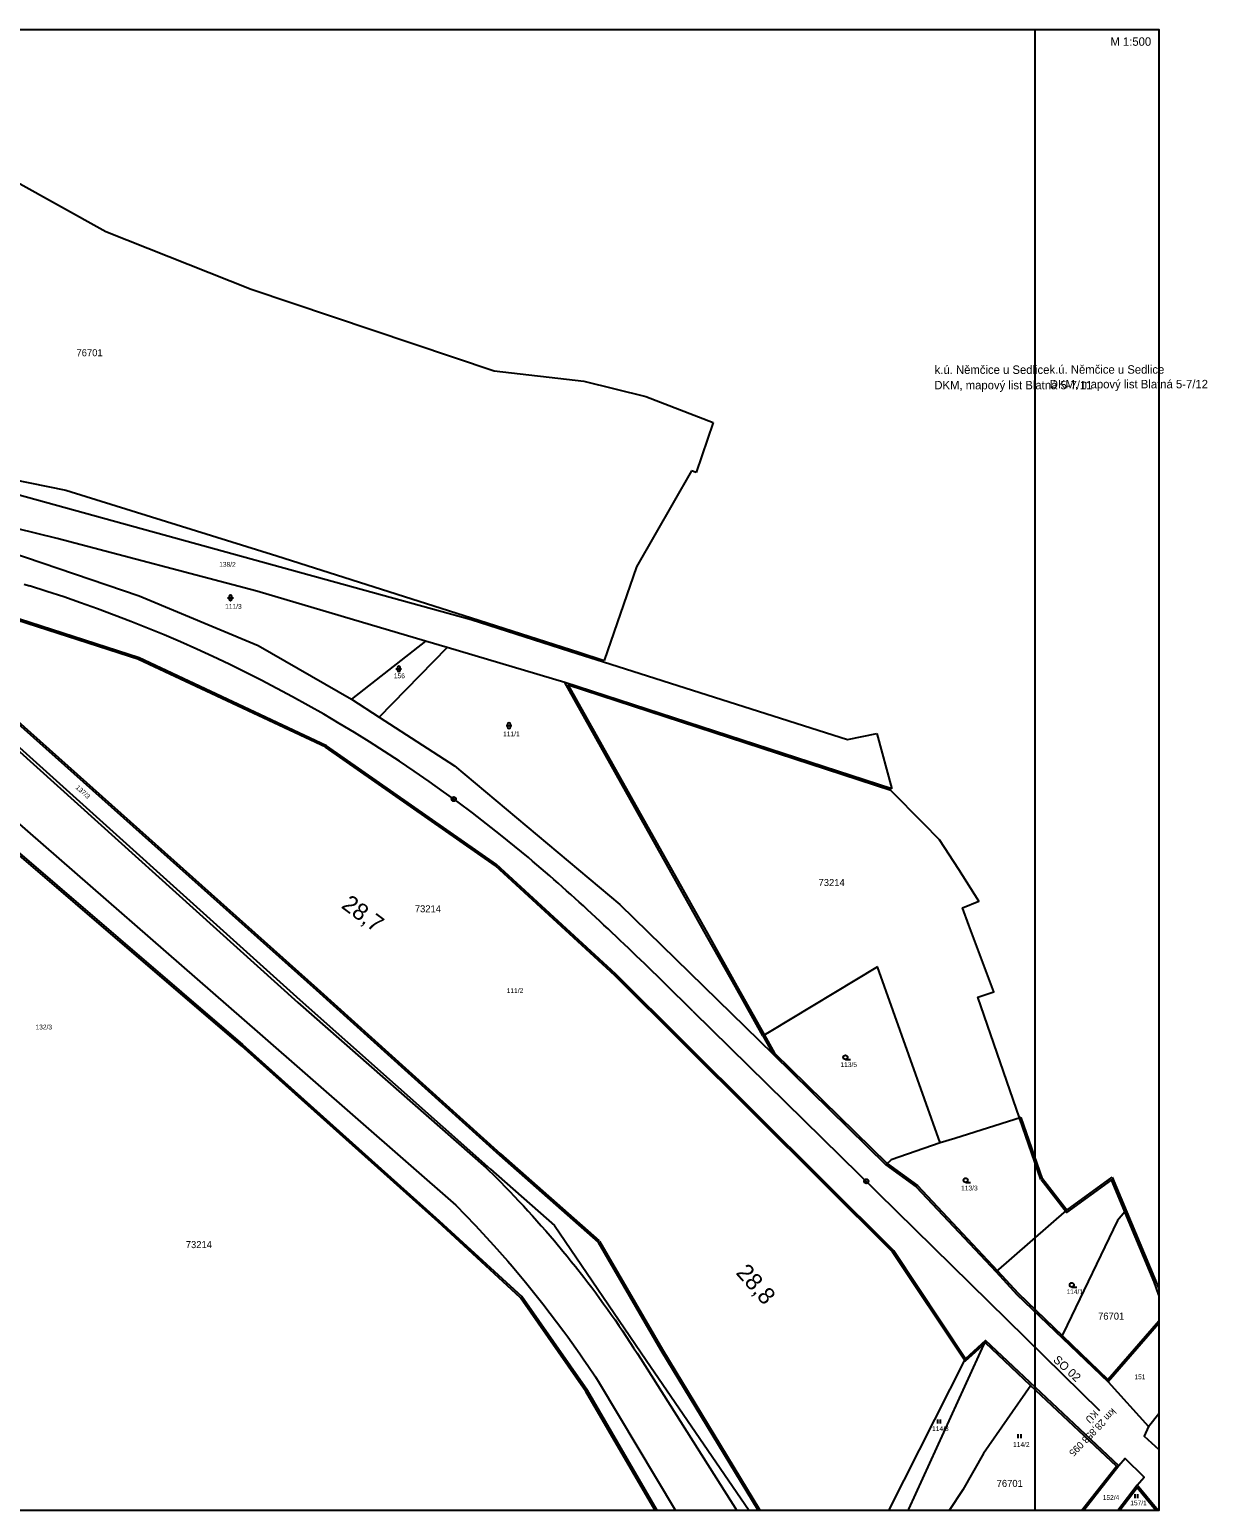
# Model space of a CAD drawing. Extents: x -792659 to -786947, y -1118170 to -1109641.
# Drawn here: x -789553.7 to -789344.4, y -1114466.8 to -1114203.8 of the extents above; entities that cross this region are included whole.
import ezdxf

# ---------------------------------------------------------------- set-up
doc = ezdxf.new("R2010")
doc.units = 0
doc.layers.add('1', color=7, linetype='Continuous')
doc.layers.add('Značky kultur', color=7, linetype='Continuous')

msp = doc.modelspace()

# ---------------------------------------------------------------- linework, layer by layer
at = {"layer": '1'}
for p, q in [((-789375, -1114466.81), (-789375, -1114203.77)), ((-789556.43, -1114230.59), (-789540.11, -1114239.63)), ((-789540.11, -1114239.63), (-789514.28, -1114249.87)), ((-789514.28, -1114249.87), (-789471.09, -1114264.39)), ((-789471.09, -1114264.39), (-789455.16, -1114266.24)), ((-789455.16, -1114266.24), (-789444.18, -1114268.92)), ((-789444.18, -1114268.92), (-789432.19, -1114273.58)), ((-789432.19, -1114273.58), (-789435.21, -1114282.44)), ((-789562.23, -1114284.54), (-789475.21, -1114308.57)), ((-789436.06, -1114282.16), (-789445.82, -1114299.21)), ((-789435.21, -1114282.44), (-789436.06, -1114282.16)), ((-789548.79, -1114294.18), (-789562.23, -1114290.83)), ((-789513.31, -1114303.51), (-789548.79, -1114294.18)), ((-789557.19, -1114296.51), (-789534.19, -1114304.37)), ((-789445.82, -1114299.21), (-789451.57, -1114315.81)), ((-789534.19, -1114304.37), (-789513.07, -1114313.2)), ((-789483.32, -1114312.4), (-789513.31, -1114303.51)), ((-789534.27, -1114315.67), (-789561.47, -1114306.89)), ((-789534.18, -1114315.38), (-789561.38, -1114306.6)), ((-789475.21, -1114308.57), (-789456.17, -1114314.65)), ((-789513.07, -1114313.2), (-789496.46, -1114322.71)), ((-789483.32, -1114312.4), (-789496.46, -1114322.71)), ((-789491.56, -1114325.89), (-789479.44, -1114313.55)), ((-789479.44, -1114313.55), (-789483.32, -1114312.4)), ((-789458.58, -1114319.72), (-789479.44, -1114313.55)), ((-789501.04, -1114331.26), (-789534.31, -1114315.65)), ((-789500.91, -1114330.99), (-789534.18, -1114315.38)), ((-789456.17, -1114314.65), (-789451.67, -1114316.09)), ((-789451.67, -1114316.09), (-789408.31, -1114329.88)), ((-789562.1, -1114321.39), (-789502.74, -1114374.33)), ((-789561.9, -1114321.17), (-789502.54, -1114374.11)), ((-789433.25, -1114364.91), (-789458.58, -1114319.72)), ((-789400.45, -1114338.66), (-789458.58, -1114319.72)), ((-789496.46, -1114322.71), (-789491.56, -1114325.89)), ((-789563.81, -1114324.53), (-789505.98, -1114376.61)), ((-789562.23, -1114325.2), (-789505.63, -1114376.09)), ((-789491.56, -1114325.89), (-789478.18, -1114334.57)), ((-789408.31, -1114329.88), (-789403.1, -1114328.81)), ((-789403.1, -1114328.81), (-789400.45, -1114338.66)), ((-789470.85, -1114352.34), (-789501.08, -1114331.24)), ((-789470.68, -1114352.09), (-789500.91, -1114330.99)), ((-789478.18, -1114334.57), (-789448.8, -1114359.16)), ((-789562.23, -1114339.03), (-789512.77, -1114382.14)), ((-789562.23, -1114344.31), (-789515.81, -1114384.07)), ((-789449.67, -1114371.78), (-789470.88, -1114352.31)), ((-789449.47, -1114371.56), (-789470.68, -1114352.09)), ((-789448.8, -1114359.16), (-789421.56, -1114385.77)), ((-789428.26, -1114373.81), (-789433.25, -1114364.91)), ((-789400.13, -1114420.69), (-789449.47, -1114371.56)), ((-789402.98, -1114370.28), (-789422.27, -1114381.87)), ((-789391.84, -1114401.52), (-789402.98, -1114370.28)), ((-789502.54, -1114374.11), (-789469.97, -1114403.5)), ((-789400.34, -1114420.9), (-789449.68, -1114371.77)), ((-789423.37, -1114382.53), (-789428.26, -1114373.81)), ((-789505.98, -1114376.61), (-789472.53, -1114405.97)), ((-789505.63, -1114376.09), (-789471.74, -1114406.17)), ((-789502.74, -1114374.33), (-789470.17, -1114403.72)), ((-789435.79, -1114378.12), (-789363.55, -1114449.05)), ((-789435.79, -1114378.12), (-789363.55, -1114449.05)), ((-789435.79, -1114378.12), (-789363.55, -1114449.05)), ((-789422.27, -1114381.87), (-789423.37, -1114382.53)), ((-789515.81, -1114384.07), (-789480.88, -1114415.35)), ((-789512.77, -1114382.14), (-789477.93, -1114412.6)), ((-789423.37, -1114382.53), (-789421.56, -1114385.77)), ((-789421.56, -1114385.77), (-789401.5, -1114405.4)), ((-789377.47, -1114397), (-789389.24, -1114400.76)), ((-789373.69, -1114407.91), (-789377.47, -1114397)), ((-789391.84, -1114401.52), (-789400.58, -1114404.52)), ((-789389.24, -1114400.76), (-789391.84, -1114401.52)), ((-789470.17, -1114403.72), (-789452.65, -1114419.15)), ((-789469.97, -1114403.49), (-789452.45, -1114418.92)), ((-789400.58, -1114404.52), (-789401.5, -1114405.4)), ((-789401.5, -1114405.4), (-789396.12, -1114409.35)), ((-789472.53, -1114405.97), (-789470.84, -1114407.63)), ((-789471.74, -1114406.17), (-789460.39, -1114416.23)), ((-789470.84, -1114407.63), (-789470.01, -1114408.47)), ((-789369.37, -1114413.5), (-789373.69, -1114407.91)), ((-789369.37, -1114413.5), (-789361.3, -1114407.6)), ((-789361.3, -1114407.6), (-789353, -1114427.42)), ((-789470.01, -1114408.47), (-789469.18, -1114409.31)), ((-789469.18, -1114409.31), (-789468.35, -1114410.16)), ((-789468.35, -1114410.16), (-789467.54, -1114411.01)), ((-789467.54, -1114411.01), (-789466.72, -1114411.87)), ((-789396.12, -1114409.35), (-789381.93, -1114424.44)), ((-789477.93, -1114412.6), (-789474.5, -1114416.13)), ((-789466.72, -1114411.87), (-789465.91, -1114412.73)), ((-789465.91, -1114412.73), (-789465.11, -1114413.6)), ((-789465.11, -1114413.6), (-789464.32, -1114414.48)), ((-789381.93, -1114424.44), (-789369.37, -1114413.5)), ((-789480.88, -1114415.35), (-789466.19, -1114428.84)), ((-789474.5, -1114416.13), (-789471.16, -1114419.75)), ((-789464.32, -1114414.48), (-789463.53, -1114415.36)), ((-789463.53, -1114415.36), (-789462.74, -1114416.24)), ((-789462.74, -1114416.24), (-789461.96, -1114417.13)), ((-789460.39, -1114416.23), (-789444.12, -1114440.1)), ((-789360.35, -1114415.34), (-789369.28, -1114433.92)), ((-789359.04, -1114413.79), (-789360.35, -1114415.34)), ((-789461.96, -1114417.13), (-789461.19, -1114418.02)), ((-789461.19, -1114418.02), (-789460.42, -1114418.92)), ((-789460.42, -1114418.92), (-789458.9, -1114420.74)), ((-789471.16, -1114419.75), (-789468.71, -1114422.52)), ((-789458.9, -1114420.74), (-789458.15, -1114421.65)), ((-789452.65, -1114419.15), (-789441.48, -1114438.37)), ((-789452.39, -1114419), (-789441.22, -1114438.22)), ((-789387.36, -1114439.86), (-789400.13, -1114420.69)), ((-789468.71, -1114422.52), (-789467.91, -1114423.45)), ((-789467.91, -1114423.45), (-789465.54, -1114426.27)), ((-789458.15, -1114421.65), (-789457.41, -1114422.57)), ((-789457.41, -1114422.57), (-789456.67, -1114423.5)), ((-789456.67, -1114423.5), (-789455.21, -1114425.36)), ((-789465.54, -1114426.27), (-789462.45, -1114430.11)), ((-789455.21, -1114425.36), (-789454.49, -1114426.3)), ((-789454.49, -1114426.3), (-789453.78, -1114427.24)), ((-789381.93, -1114424.44), (-789378.22, -1114428.46)), ((-789454.55, -1114445.52), (-789466.19, -1114428.84)), ((-789453.78, -1114427.24), (-789453.07, -1114428.19)), ((-789453.07, -1114428.19), (-789452.37, -1114429.14)), ((-789452.37, -1114429.14), (-789451.67, -1114430.09)), ((-789378.22, -1114428.46), (-789362.04, -1114444)), ((-789378.01, -1114428.24), (-789361.83, -1114443.78)), ((-789462.45, -1114430.11), (-789458.74, -1114435.02)), ((-789451.67, -1114430.09), (-789450.98, -1114431.06)), ((-789450.98, -1114431.06), (-789450.3, -1114432.02)), ((-789450.3, -1114432.02), (-789449.62, -1114432.99)), ((-789449.62, -1114432.99), (-789448.95, -1114433.97)), ((-789448.95, -1114433.97), (-789448.29, -1114434.94)), ((-789369.28, -1114433.92), (-789370.2, -1114435.75)), ((-789353, -1114433.59), (-789362.04, -1114444)), ((-789458.74, -1114435.02), (-789458.01, -1114436.01)), ((-789458.01, -1114436.01), (-789457.29, -1114437.01)), ((-789457.29, -1114437.01), (-789456.58, -1114438.02)), ((-789448.29, -1114434.94), (-789448.29, -1114434.94)), ((-789448.29, -1114434.94), (-789446.98, -1114436.91)), ((-789446.98, -1114436.91), (-789446.33, -1114437.91)), ((-789383.79, -1114436.65), (-789397.47, -1114466.61)), ((-789383.79, -1114436.65), (-789387.36, -1114439.86)), ((-789360.15, -1114458.92), (-789383.79, -1114436.65)), ((-789456.58, -1114438.02), (-789455.88, -1114439.02)), ((-789455.88, -1114439.02), (-789455.18, -1114440.04)), ((-789446.33, -1114437.91), (-789445.69, -1114438.9)), ((-789445.69, -1114438.9), (-789445.06, -1114439.9)), ((-789445.06, -1114439.9), (-789427.97, -1114466.81)), ((-789441.48, -1114438.37), (-789424.2, -1114466.81)), ((-789441.22, -1114438.21), (-789423.95, -1114466.65)), ((-789401, -1114466.81), (-789387.36, -1114439.86)), ((-789455.18, -1114440.04), (-789454.48, -1114441.05)), ((-789454.48, -1114441.05), (-789453.11, -1114443.1)), ((-789444.12, -1114440.1), (-789425.82, -1114466.81)), ((-789453.11, -1114443.1), (-789452.44, -1114444.13)), ((-789452.44, -1114444.13), (-789438.87, -1114466.81)), ((-789375.75, -1114444.64), (-789384.14, -1114456.72)), ((-789362.04, -1114444), (-789354.83, -1114451.89)), ((-789442.15, -1114466.81), (-789454.55, -1114445.52)), ((-789354.83, -1114451.89), (-789353, -1114449.6)), ((-789354.83, -1114451.89), (-789355.6, -1114453.64)), ((-789355.6, -1114453.64), (-789353, -1114455.98)), ((-789384.14, -1114456.72), (-789387.82, -1114463.14)), ((-789359, -1114457.59), (-789360.15, -1114458.92)), ((-789355.65, -1114460.93), (-789359, -1114457.59)), ((-789360.15, -1114458.92), (-789366.36, -1114466.81)), ((-789356.86, -1114462.31), (-789355.65, -1114460.93)), ((-789387.82, -1114463.14), (-789390.27, -1114466.81)), ((-789356.86, -1114462.31), (-789360.31, -1114466.81)), ((-789353.13, -1114466.81), (-789356.86, -1114462.31)), ((-789397.47, -1114466.61), (-789397.6, -1114466.81))]:
    msp.add_line(p, q, dxfattribs=at)
msp.add_lwpolyline([(-789729.37, -1114203.77), (-789353, -1114203.77), (-789353, -1114466.81), (-789729.37, -1114466.81)], close=True, dxfattribs=at)
for points in [[(-789674.01, -1114222.23), (-789653.09, -1114241.04), (-789626.09, -1114265.17), (-789585.65, -1114277.76), (-789547.21, -1114285.57), (-789509.71, -1114297.22), (-789475.12, -1114308.28), (-789456.08, -1114314.36), (-789451.57, -1114315.81)], [(-789557.19, -1114296.51), (-789534.19, -1114304.37), (-789513.07, -1114313.2), (-789496.46, -1114322.71), (-789491.56, -1114325.89), (-789478.18, -1114334.57), (-789448.8, -1114359.16), (-789421.56, -1114385.77), (-789401.5, -1114405.4), (-789396.12, -1114409.35), (-789381.93, -1114424.44), (-789378.22, -1114428.46), (-789362.04, -1114444), (-789354.83, -1114451.89), (-789355.6, -1114453.64), (-789353, -1114455.98), (-789353, -1114466.81), (-789353.13, -1114466.81), (-789356.86, -1114462.31), (-789355.65, -1114460.93), (-789359, -1114457.59), (-789360.15, -1114458.92), (-789383.79, -1114436.65), (-789387.36, -1114439.86), (-789400.13, -1114420.69), (-789449.47, -1114371.56), (-789470.68, -1114352.09), (-789500.91, -1114330.99), (-789534.18, -1114315.38), (-789561.38, -1114306.6)], [(-789554.62, -1114302.3), (-789553.66, -1114302.59)], [(-789554.62, -1114302.3), (-789553.66, -1114302.59)], [(-789554.62, -1114302.3), (-789553.66, -1114302.59)], [(-789554.62, -1114302.3), (-789553.66, -1114302.59)], [(-789373.97, -1114408.01), (-789377.75, -1114397.1), (-789378.87, -1114393.82), (-789385.15, -1114375.67), (-789382.31, -1114374.69), (-789386.76, -1114362.85), (-789387.9, -1114359.79), (-789385.02, -1114358.6), (-789388.58, -1114352.99), (-789391.97, -1114347.67), (-789394.89, -1114344.71), (-789400.61, -1114338.92), (-789457.94, -1114320.24), (-789432.99, -1114364.76), (-789428, -1114373.66), (-789423.11, -1114382.38), (-789421.32, -1114385.59), (-789401.31, -1114405.17), (-789395.92, -1114409.12), (-789381.71, -1114424.24), (-789378.01, -1114428.25), (-789370.13, -1114435.81)], [(-789442.5, -1114466.81), (-789454.8, -1114445.68), (-789466.42, -1114429.04), (-789481.08, -1114415.57), (-789516.01, -1114384.3), (-789575.49, -1114333.35), (-789576.46, -1114335.45), (-789599.6, -1114385.9), (-789602.99, -1114393.32), (-789604.59, -1114396.8)], [(-789435.79, -1114378.12), (-789436.5, -1114377.42), (-789437.21, -1114376.72), (-789437.93, -1114376.02), (-789438.64, -1114375.32), (-789439.36, -1114374.62), (-789440.07, -1114373.92), (-789440.78, -1114373.22), (-789441.5, -1114372.52), (-789442.22, -1114371.82), (-789442.93, -1114371.13), (-789443.65, -1114370.43), (-789444.37, -1114369.73), (-789445.09, -1114369.04), (-789445.81, -1114368.34), (-789446.53, -1114367.65), (-789447.25, -1114366.96), (-789447.97, -1114366.27), (-789448.7, -1114365.58), (-789449.42, -1114364.89), (-789450.15, -1114364.2), (-789450.88, -1114363.52), (-789451.6, -1114362.83), (-789452.33, -1114362.15), (-789453.07, -1114361.47), (-789453.8, -1114360.79), (-789454.54, -1114360.11), (-789455.27, -1114359.44), (-789456.01, -1114358.76), (-789456.75, -1114358.09), (-789457.5, -1114357.42), (-789458.24, -1114356.75), (-789458.99, -1114356.09), (-789459.74, -1114355.42), (-789460.49, -1114354.76), (-789461.24, -1114354.11), (-789462, -1114353.45), (-789462.75, -1114352.8), (-789463.51, -1114352.15), (-789464.28, -1114351.5), (-789465.04, -1114350.86)], [(-789435.79, -1114378.12), (-789436.5, -1114377.42), (-789437.21, -1114376.72), (-789437.93, -1114376.02), (-789438.64, -1114375.32), (-789439.36, -1114374.62), (-789440.07, -1114373.92), (-789440.78, -1114373.22), (-789441.5, -1114372.52), (-789442.22, -1114371.82), (-789442.93, -1114371.13), (-789443.65, -1114370.43), (-789444.37, -1114369.73), (-789445.09, -1114369.04), (-789445.81, -1114368.34), (-789446.53, -1114367.65), (-789447.25, -1114366.96), (-789447.97, -1114366.27), (-789448.7, -1114365.58), (-789449.42, -1114364.89), (-789450.15, -1114364.2), (-789450.88, -1114363.52), (-789451.6, -1114362.83), (-789452.33, -1114362.15), (-789453.07, -1114361.47), (-789453.8, -1114360.79), (-789454.54, -1114360.11), (-789455.27, -1114359.44), (-789456.01, -1114358.76), (-789456.75, -1114358.09), (-789457.5, -1114357.42), (-789458.24, -1114356.75), (-789458.99, -1114356.09), (-789459.74, -1114355.42), (-789460.49, -1114354.76), (-789461.24, -1114354.11), (-789462, -1114353.45), (-789462.75, -1114352.8), (-789463.51, -1114352.15), (-789464.28, -1114351.5), (-789465.04, -1114350.86)], [(-789435.79, -1114378.12), (-789436.5, -1114377.42), (-789437.21, -1114376.72), (-789437.93, -1114376.02), (-789438.64, -1114375.32), (-789439.36, -1114374.62), (-789440.07, -1114373.92), (-789440.78, -1114373.22), (-789441.5, -1114372.52), (-789442.22, -1114371.82), (-789442.93, -1114371.13), (-789443.65, -1114370.43), (-789444.37, -1114369.73), (-789445.09, -1114369.04), (-789445.81, -1114368.34), (-789446.53, -1114367.65), (-789447.25, -1114366.96), (-789447.97, -1114366.27), (-789448.7, -1114365.58), (-789449.42, -1114364.89), (-789450.15, -1114364.2), (-789450.88, -1114363.52), (-789451.6, -1114362.83), (-789452.33, -1114362.15), (-789453.07, -1114361.47), (-789453.8, -1114360.79), (-789454.54, -1114360.11), (-789455.27, -1114359.44), (-789456.01, -1114358.76), (-789456.75, -1114358.09), (-789457.5, -1114357.42), (-789458.24, -1114356.75), (-789458.99, -1114356.09), (-789459.74, -1114355.42), (-789460.49, -1114354.76), (-789461.24, -1114354.11), (-789462, -1114353.45), (-789462.75, -1114352.8), (-789463.51, -1114352.15), (-789464.28, -1114351.5), (-789465.04, -1114350.86)], [(-789359.04, -1114413.79), (-789361.43, -1114408.07), (-789369.43, -1114413.91), (-789373.93, -1114408.09)], [(-789353, -1114428.57), (-789353.82, -1114426.24), (-789359.04, -1114413.79)], [(-789375.79, -1114444.61), (-789383.79, -1114437.06), (-789387.42, -1114440.32), (-789400.38, -1114420.86)], [(-789370.13, -1114435.81), (-789362.06, -1114443.57), (-789353, -1114433.13)], [(-789366.74, -1114466.81), (-789360.56, -1114458.95), (-789375.79, -1114444.61)], [(-789353.52, -1114466.81), (-789356.85, -1114462.79), (-789359.93, -1114466.81)]]:
    msp.add_lwpolyline(points, dxfattribs=at)
for centre in [(-789478.31, -1114340.46), (-789478.3, -1114340.45), (-789405.01, -1114408.35), (-789404.99, -1114408.34)]:
    msp.add_circle(centre, 0.375, dxfattribs=at)
msp.add_arc((-789628.9, -1114546.24), 255, 50.0141, 72.8377, dxfattribs=at)
msp.add_arc((-789628.9, -1114546.24), 255, 50.0141, 72.8377, dxfattribs=at)
msp.add_arc((-789628.9, -1114546.24), 255, 50.0141, 72.8377, dxfattribs=at)
at = {"layer": 'Značky kultur'}
for p, q in [((-789518.47, -1114304.73), (-789517.46, -1114304.73)), ((-789518.22, -1114304.48), (-789518.22, -1114304.98)), ((-789517.71, -1114304.98), (-789517.71, -1114304.48)), ((-789488.57, -1114317.31), (-789487.57, -1114317.31)), ((-789488.32, -1114317.06), (-789488.32, -1114317.56)), ((-789487.82, -1114317.56), (-789487.82, -1114317.06)), ((-789468.98, -1114327.41), (-789467.98, -1114327.41)), ((-789468.73, -1114327.16), (-789468.73, -1114327.66)), ((-789468.23, -1114327.66), (-789468.23, -1114327.16)), ((-789408.7, -1114386.72), (-789407.82, -1114386.72)), ((-789387.33, -1114408.55), (-789386.46, -1114408.55)), ((-789368.48, -1114427.14), (-789367.61, -1114427.14)), ((-789392.3, -1114451.4), (-789392.3, -1114450.65)), ((-789391.8, -1114451.4), (-789391.8, -1114450.65)), ((-789377.99, -1114454.01), (-789377.99, -1114453.26)), ((-789377.49, -1114454.01), (-789377.49, -1114453.26)), ((-789357.24, -1114464.65), (-789357.24, -1114463.9)), ((-789356.74, -1114464.65), (-789356.74, -1114463.9))]:
    msp.add_line(p, q, dxfattribs=at)
for centre in [(-789408.7, -1114386.34), (-789387.33, -1114408.17), (-789368.48, -1114426.76)]:
    msp.add_circle(centre, 0.375, dxfattribs=at)
for centre, start, end in [((-789517.97, -1114304.48), 0, 180), ((-789517.97, -1114304.97), 180, 359.9879), ((-789488.07, -1114317.06), 0, 180), ((-789488.07, -1114317.56), 180, 359.9879), ((-789468.48, -1114327.16), 0, 180), ((-789468.48, -1114327.66), 180, 359.9879)]:
    msp.add_arc(centre, 0.25, start, end, dxfattribs=at)

# ---------------------------------------------------------------- texts
at = {"layer": '1'}
for s, height, p in [('M 1:500', 1.5, (-789361.62, -1114206.64)), ('76701', 1.25, (-789545.33, -1114261.79)), ('k.ú. Němčice u Sedlice', 1.5, (-789392.85, -1114264.93)), ('k.ú. Němčice u Sedlice', 1.5, (-789372.44, -1114264.89)), ('DKM, mapový list Blatná 5-7/11', 1.5, (-789392.9, -1114267.67)), ('DKM, mapový list Blatná 5-7/12', 1.5, (-789372.38, -1114267.49)), ('138/2', 0.85, (-789519.97, -1114299.19)), ('111/3', 0.85, (-789518.91, -1114306.66)), ('156', 0.85, (-789488.94, -1114318.99)), ('111/1', 0.85, (-789469.52, -1114329.3)), ('73214', 1.25, (-789413.48, -1114355.91)), ('73214', 1.25, (-789485.21, -1114360.57)), ('111/2', 0.85, (-789468.87, -1114374.9)), ('132/3', 0.85, (-789552.61, -1114381.38)), ('113/5', 0.85, (-789409.58, -1114388.05)), ('113/3', 0.85, (-789388.14, -1114409.98)), ('73214', 1.25, (-789525.91, -1114420.22)), ('114/1', 0.85, (-789369.42, -1114428.39)), ('76701', 1.25, (-789363.81, -1114432.92)), ('151', 0.85, (-789357.35, -1114443.51)), ('114/3', 0.85, (-789393.3, -1114452.71)), ('114/2', 0.85, (-789378.92, -1114455.54)), ('76701', 1.25, (-789381.83, -1114462.64)), ('152/4', 0.85, (-789362.98, -1114464.95)), ('157/1', 0.85, (-789358.09, -1114465.91))]:
    msp.add_text(s, height=height, dxfattribs=at).set_placement(p)
for s, height, rotation, p in [('137/3', 0.85, 318.2948, (-789545.57, -1114338.52)), ('28,7', 3, 323.4039, (-789498.44, -1114359.66)), ('28,8', 3, 311.6833, (-789428.3, -1114424.68)), ('SO 02', 1.5, 317.5674, (-789371.91, -1114440.24)), ('km 28,858 095', 1.25, 225.5203, (-789361.33, -1114448.57)), ('KÚ', 1.25, 225.5203, (-789364.54, -1114448.91))]:
    msp.add_text(s, height=height, rotation=rotation, dxfattribs=at).set_placement(p)

doc.saveas('drawing.dxf')
